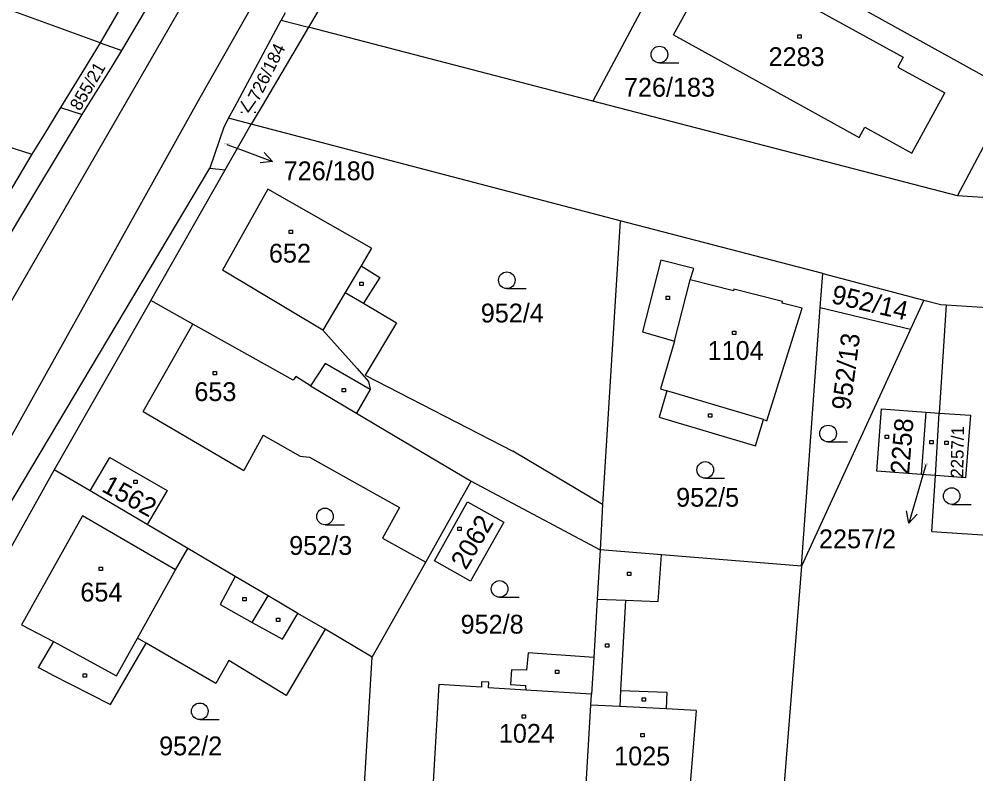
# Model space of a CAD drawing. Extents: x -711879 to -711361, y -1048782 to -1048177.
# Drawn here: x -711571.3 to -711485, y -1048372.4 to -1048304.3 of the extents above; entities that cross this region are included whole.
import ezdxf

# ---------------------------------------------------------------- set-up
doc = ezdxf.new("R2010")
doc.units = 0
for name, color, linetype in [('Vrstva 1', 7, 'Continuous'), ('Vrstva 13', 7, 'Continuous'), ('Vrstva 14', 7, 'Continuous'), ('Vrstva 15', 7, 'Continuous'), ('Vrstva 16', 7, 'Continuous'), ('Vrstva 2', 7, 'Continuous'), ('Vrstva 23', 7, 'Continuous'), ('Vrstva 25', 7, 'Continuous'), ('Vrstva 46', 7, 'Continuous')]:
    doc.layers.add(name, color=color, linetype=linetype)

msp = doc.modelspace()

# ---------------------------------------------------------------- linework, layer by layer
at = {"layer": 'Vrstva 1'}
for p, q in [((-711524.36, -1048257.61), (-711555.05, -1048311.45)), ((-711548.53, -1048279.74), (-711564.04, -1048306.47)), ((-711562.07, -1048307.17), (-711547.11, -1048281.75)), ((-711532.03, -1048282.6), (-711545.23, -1048305.07)), ((-711545.71, -1048284.16), (-711558.97, -1048307.13)), ((-711510.59, -1048294.89), (-711519.58, -1048311.73)), ((-711481.7, -1048310.92), (-711510.59, -1048294.89)), ((-711564.04, -1048306.47), (-711576.93, -1048301.82)), ((-711547.33, -1048303.79), (-711547.7, -1048304.44)), ((-711551.88, -1048312.25), (-711547.7, -1048304.44)), ((-711547.7, -1048304.44), (-711545.23, -1048305.07)), ((-711545.23, -1048305.07), (-711546.26, -1048306.81)), ((-711519.58, -1048311.73), (-711545.23, -1048305.07)), ((-711558.97, -1048307.13), (-711582.21, -1048347.23)), ((-711564.04, -1048306.47), (-711565.04, -1048308.11)), ((-711564.04, -1048306.47), (-711562.07, -1048307.17)), ((-711562.95, -1048308.63), (-711562.07, -1048307.17)), ((-711546.26, -1048306.81), (-711549.42, -1048312.18)), ((-711565.04, -1048308.11), (-711565.22, -1048308.4)), ((-711565.22, -1048308.4), (-711567.62, -1048312.33)), ((-711565.65, -1048312.95), (-711562.95, -1048308.63)), ((-711587.33, -1048311.04), (-711570.19, -1048316.54)), ((-711555.05, -1048311.45), (-711583.43, -1048362.34)), ((-711486.65, -1048320.28), (-711481.7, -1048310.92)), ((-711567.62, -1048312.33), (-711569.16, -1048314.85)), ((-711567.62, -1048312.33), (-711565.65, -1048312.95)), ((-711552.44, -1048313.29), (-711551.88, -1048312.25)), ((-711549.42, -1048312.18), (-711550.4, -1048313.82)), ((-711486.65, -1048320.28), (-711519.58, -1048311.73)), ((-711569.92, -1048320.04), (-711565.65, -1048312.95)), ((-711552.44, -1048313.29), (-711552.87, -1048314.09)), ((-711550.4, -1048313.82), (-711552.44, -1048313.29)), ((-711552.87, -1048314.09), (-711554.12, -1048317.79)), ((-711552.75, -1048317.94), (-711550.4, -1048313.82)), ((-711517.11, -1048322.54), (-711550.4, -1048313.82)), ((-711569.16, -1048314.85), (-711570.19, -1048316.54)), ((-711570.19, -1048316.54), (-711580.92, -1048334.45)), ((-711584.04, -1048367.95), (-711554.12, -1048317.79)), ((-711559.47, -1048329.72), (-711552.75, -1048317.94)), ((-711554.12, -1048317.79), (-711552.75, -1048317.94)), ((-711588.19, -1048350.31), (-711569.92, -1048320.04)), ((-711548.89, -1048319.68), (-711552.99, -1048326.98)), ((-711539.55, -1048325), (-711548.89, -1048319.68)), ((-711462.88, -1048321.96), (-711486.65, -1048320.28)), ((-711517.11, -1048322.54), (-711518.68, -1048348.13)), ((-711498.82, -1048327.29), (-711517.11, -1048322.54)), ((-711539.55, -1048325), (-711540.49, -1048326.6)), ((-711513.42, -1048326.1), (-711515.08, -1048332.56)), ((-711510.46, -1048326.85), (-711513.42, -1048326.1)), ((-711543.93, -1048332.41), (-711552.99, -1048326.98)), ((-711540.49, -1048326.6), (-711538.8, -1048327.64)), ((-711510.77, -1048327.87), (-711510.46, -1048326.85)), ((-711538.8, -1048327.64), (-711540.26, -1048329.98)), ((-711506.86, -1048328.85), (-711510.77, -1048327.87)), ((-711499.06, -1048330.36), (-711498.82, -1048327.29)), ((-711498.82, -1048327.29), (-711489.7, -1048329.69)), ((-711506.83, -1048328.7), (-711506.86, -1048328.85)), ((-711502.45, -1048329.81), (-711506.83, -1048328.7)), ((-711559.47, -1048329.72), (-711568.18, -1048345.01)), ((-711555.66, -1048331.85), (-711559.47, -1048329.72)), ((-711489.7, -1048329.69), (-711490.91, -1048332.3)), ((-711489.7, -1048329.69), (-711488.17, -1048330.09)), ((-711540.26, -1048329.98), (-711537.29, -1048331.74)), ((-711503.86, -1048340.57), (-711500.68, -1048330.41)), ((-711502.48, -1048329.96), (-711502.45, -1048329.81)), ((-711500.68, -1048330.41), (-711502.48, -1048329.96)), ((-711500.73, -1048353.71), (-711499.06, -1048330.36)), ((-711499.06, -1048330.36), (-711490.91, -1048332.3)), ((-711487.69, -1048330.12), (-711488.3, -1048339.88)), ((-711488.17, -1048330.09), (-711487.69, -1048330.12)), ((-711487.69, -1048330.12), (-711468.27, -1048331.34)), ((-711560.16, -1048339.74), (-711555.66, -1048331.85)), ((-711546.6, -1048336.92), (-711555.66, -1048331.85)), ((-711537.29, -1048331.74), (-711540.13, -1048336.47)), ((-711490.91, -1048332.3), (-711500.73, -1048353.71)), ((-711543.93, -1048332.41), (-711540.85, -1048335.86)), ((-711515.08, -1048332.56), (-711512.2, -1048333.41)), ((-711512.2, -1048333.41), (-711513.47, -1048337.71)), ((-711543.74, -1048335.41), (-711545.05, -1048337.44)), ((-711539.66, -1048337.75), (-711543.74, -1048335.41)), ((-711546.37, -1048336.57), (-711546.6, -1048336.92)), ((-711545.05, -1048337.44), (-711546.37, -1048336.57)), ((-711540.85, -1048335.86), (-711539.8, -1048337.04)), ((-711540.13, -1048336.47), (-711526.79, -1048343.33)), ((-711545.05, -1048337.44), (-711540.9, -1048339.9)), ((-711539.8, -1048337.04), (-711539.66, -1048337.75)), ((-711512.89, -1048337.89), (-711513.59, -1048340.26)), ((-711513.47, -1048337.71), (-711512.89, -1048337.89)), ((-711560.16, -1048339.74), (-711551.07, -1048345.07)), ((-711540.9, -1048339.9), (-711538.87, -1048341.1)), ((-711493.94, -1048345.11), (-711493.51, -1048339.51)), ((-711493.51, -1048339.51), (-711489.5, -1048339.79)), ((-711489.5, -1048339.79), (-711489.93, -1048345.42)), ((-711489.5, -1048339.79), (-711488.3, -1048339.88)), ((-711488.65, -1048345.52), (-711488.3, -1048339.88)), ((-711488.3, -1048339.88), (-711485.48, -1048340.08)), ((-711485.48, -1048340.08), (-711485.92, -1048345.73)), ((-711513.59, -1048340.26), (-711504.88, -1048342.84)), ((-711504.88, -1048342.84), (-711504.17, -1048340.47)), ((-711504.17, -1048340.47), (-711503.86, -1048340.57)), ((-711538.87, -1048341.1), (-711530.54, -1048346.03)), ((-711549.31, -1048341.87), (-711551.07, -1048345.07)), ((-711518.68, -1048348.13), (-711526.79, -1048343.33)), ((-711564.95, -1048346.91), (-711563.16, -1048343.88)), ((-711563.16, -1048343.88), (-711557.99, -1048346.87)), ((-711568.18, -1048345.01), (-711582.56, -1048370.66)), ((-711564.95, -1048346.91), (-711568.18, -1048345.01)), ((-711489.93, -1048345.42), (-711493.94, -1048345.11)), ((-711533.2, -1048350.75), (-711530.54, -1048346.03)), ((-711530.54, -1048346.03), (-711518.92, -1048352.21)), ((-711488.65, -1048345.52), (-711489.93, -1048345.42)), ((-711488.97, -1048350.58), (-711488.65, -1048345.52)), ((-711485.92, -1048345.73), (-711488.65, -1048345.52)), ((-711559.8, -1048349.94), (-711564.95, -1048346.91)), ((-711557.99, -1048346.87), (-711559.8, -1048349.94)), ((-711533.87, -1048353.2), (-711530.87, -1048347.88)), ((-711530.87, -1048347.88), (-711527.6, -1048349.72)), ((-711518.68, -1048348.13), (-711518.92, -1048352.21)), ((-711565.64, -1048349.16), (-711571.12, -1048358.99)), ((-711557.23, -1048354.03), (-711565.64, -1048349.16)), ((-711556.11, -1048352.11), (-711559.8, -1048349.94)), ((-711527.6, -1048349.72), (-711530.6, -1048355.05)), ((-711534.65, -1048353.32), (-711533.2, -1048350.75)), ((-711488.97, -1048350.58), (-711470.22, -1048351.75)), ((-711557.23, -1048354.03), (-711556.11, -1048352.11)), ((-711551.85, -1048354.62), (-711556.11, -1048352.11)), ((-711518.92, -1048352.21), (-711519.18, -1048356.66)), ((-711513.38, -1048352.67), (-711518.92, -1048352.21)), ((-711500.73, -1048353.71), (-711513.38, -1048352.67)), ((-711539.49, -1048361.89), (-711534.65, -1048353.32)), ((-711530.6, -1048355.05), (-711533.87, -1048353.2)), ((-711500.73, -1048353.71), (-711502.65, -1048377.83)), ((-711548.88, -1048356.37), (-711551.85, -1048354.62)), ((-711546.18, -1048357.96), (-711548.88, -1048356.37)), ((-711519.18, -1048356.66), (-711519.49, -1048361.93)), ((-711543.74, -1048359.39), (-711546.18, -1048357.96)), ((-711571.12, -1048358.99), (-711568.25, -1048360.49)), ((-711543.74, -1048359.39), (-711547.26, -1048365.37)), ((-711539.49, -1048361.89), (-711543.74, -1048359.39)), ((-711568.25, -1048360.49), (-711569.62, -1048362.84)), ((-711563.09, -1048366.18), (-711559.89, -1048360.64)), ((-711553.59, -1048364.27), (-711559.89, -1048360.64)), ((-711525.39, -1048361.52), (-711525.55, -1048363.07)), ((-711519.49, -1048361.93), (-711525.39, -1048361.52)), ((-711552.41, -1048362.22), (-711553.59, -1048364.27)), ((-711547.26, -1048365.37), (-711552.41, -1048362.22)), ((-711540.33, -1048375.71), (-711539.49, -1048361.89)), ((-711519.49, -1048361.93), (-711519.69, -1048365.25)), ((-711568.43, -1048363.47), (-711569.62, -1048362.84)), ((-711526.9, -1048363.05), (-711527.01, -1048364.37)), ((-711525.55, -1048363.07), (-711526.9, -1048363.05)), ((-711568.43, -1048363.47), (-711563.09, -1048366.18)), ((-711529.61, -1048364.13), (-711529.63, -1048364.61)), ((-711528.96, -1048364.16), (-711529.61, -1048364.13)), ((-711528.98, -1048364.66), (-711528.96, -1048364.16)), ((-711533.47, -1048364.37), (-711533.97, -1048373.17)), ((-711529.63, -1048364.61), (-711533.47, -1048364.37)), ((-711525.61, -1048364.87), (-711528.98, -1048364.66)), ((-711527.01, -1048364.37), (-711525.64, -1048364.47)), ((-711525.64, -1048364.47), (-711525.61, -1048364.87)), ((-711519.75, -1048366.23), (-711519.69, -1048365.25)), ((-711520.23, -1048374.45), (-711519.75, -1048366.23))]:
    msp.add_line(p, q, dxfattribs=at)
for points in [[(-711512.3, -1048305.77), (-711508.33, -1048298.55), (-711491.56, -1048307.79), (-711492.04, -1048308.69), (-711487.8, -1048310.99)], [(-711512.3, -1048305.77), (-711495.53, -1048315.02), (-711495.01, -1048314.08), (-711490.78, -1048316.44), (-711487.8, -1048310.99)], [(-711549.31, -1048341.87), (-711545.99, -1048343.76), (-711545.15, -1048343.86), (-711537.03, -1048348.4), (-711538.54, -1048351.16), (-711534.65, -1048353.32)]]:
    msp.add_lwpolyline(points, dxfattribs=at)
at = {"layer": 'Vrstva 13'}
for p, q in [((-711552.59, -1048315.65), (-711551.28, -1048316.14)), ((-711489.51, -1048344.55), (-711490.21, -1048346.93))]:
    msp.add_line(p, q, dxfattribs=at)
at = {"layer": 'Vrstva 16'}
for p, q in [((-711551.28, -1048316.14), (-711548.467, -1048317.184)), ((-711548.467, -1048317.184), (-711549.231, -1048316.367)), ((-711548.467, -1048317.184), (-711549.579, -1048317.304)), ((-711490.21, -1048346.93), (-711491.052, -1048349.809)), ((-711491.052, -1048349.809), (-711491.251, -1048348.708)), ((-711491.052, -1048349.809), (-711490.292, -1048348.989))]:
    msp.add_line(p, q, dxfattribs=at)
at = {"layer": 'Vrstva 2'}
for p, q in [((-711540.49, -1048326.6), (-711541.91, -1048329)), ((-711512.2, -1048333.41), (-711510.77, -1048327.87)), ((-711541.91, -1048329), (-711543.93, -1048332.41)), ((-711541.91, -1048329), (-711540.26, -1048329.98)), ((-711539.66, -1048337.75), (-711540.9, -1048339.9)), ((-711504.17, -1048340.47), (-711512.89, -1048337.89)), ((-711513.67, -1048356.88), (-711513.38, -1048352.67)), ((-711560.66, -1048360.19), (-711557.23, -1048354.03)), ((-711551.85, -1048354.62), (-711553.19, -1048357.16)), ((-711550.31, -1048358.77), (-711548.88, -1048356.37)), ((-711553.19, -1048357.16), (-711550.31, -1048358.77)), ((-711519.18, -1048356.66), (-711516.61, -1048356.77)), ((-711516.61, -1048356.77), (-711517.06, -1048364.9)), ((-711516.61, -1048356.77), (-711513.67, -1048356.88)), ((-711547.58, -1048360.29), (-711546.18, -1048357.96)), ((-711550.31, -1048358.77), (-711547.58, -1048360.29)), ((-711568.25, -1048360.49), (-711562.56, -1048363.6)), ((-711562.56, -1048363.6), (-711560.66, -1048360.19)), ((-711559.89, -1048360.64), (-711560.66, -1048360.19)), ((-711519.69, -1048365.25), (-711525.61, -1048364.87)), ((-711517.06, -1048364.9), (-711517.12, -1048366.36)), ((-711517.06, -1048364.9), (-711512.9, -1048365.06)), ((-711512.9, -1048365.06), (-711512.94, -1048366.58)), ((-711517.12, -1048366.36), (-711519.75, -1048366.23)), ((-711512.94, -1048366.58), (-711517.12, -1048366.36)), ((-711510.23, -1048366.72), (-711512.94, -1048366.58)), ((-711510.23, -1048366.72), (-711510.91, -1048374.85))]:
    msp.add_line(p, q, dxfattribs=at)
at = {"layer": 'Vrstva 23'}
for p, q in [((-711513.56, -1048308.29), (-711511.81, -1048308.29)), ((-711551.33, -1048311.745), (-711550.66, -1048312.75)), ((-711550.66, -1048312.75), (-711549.99, -1048311.745)), ((-711551.33, -1048312.75), (-711551.196, -1048312.75)), ((-711550.124, -1048312.75), (-711549.99, -1048312.75)), ((-711527.33, -1048328.65), (-711525.58, -1048328.65)), ((-711498.33, -1048342.48), (-711496.58, -1048342.48)), ((-711509.42, -1048345.76), (-711507.67, -1048345.76)), ((-711487.18, -1048348.12), (-711485.43, -1048348.12)), ((-711543.74, -1048349.96), (-711541.99, -1048349.96)), ((-711527.98, -1048356.5), (-711526.23, -1048356.5)), ((-711555.04, -1048367.54), (-711553.29, -1048367.54))]:
    msp.add_line(p, q, dxfattribs=at)
for centre in [(-711513.56, -1048307.54), (-711527.33, -1048327.9), (-711498.33, -1048341.73), (-711509.42, -1048345.01), (-711487.18, -1048347.37), (-711543.74, -1048349.21), (-711527.98, -1048355.75), (-711555.04, -1048366.79)]:
    msp.add_circle(centre, 0.75, dxfattribs=at)
at = {"layer": 'Vrstva 25'}
for p, q in [((-711501.07, -1048305.76), (-711500.77, -1048305.76)), ((-711501.07, -1048306.06), (-711501.07, -1048305.76)), ((-711500.77, -1048306.06), (-711501.07, -1048306.06)), ((-711500.77, -1048305.76), (-711500.77, -1048306.06)), ((-711546.98, -1048323.39), (-711546.68, -1048323.39)), ((-711546.98, -1048323.69), (-711546.98, -1048323.39)), ((-711546.68, -1048323.69), (-711546.98, -1048323.69)), ((-711546.68, -1048323.39), (-711546.68, -1048323.69)), ((-711540.59, -1048328.06), (-711540.29, -1048328.06)), ((-711540.59, -1048328.36), (-711540.59, -1048328.06)), ((-711540.29, -1048328.36), (-711540.59, -1048328.36)), ((-711540.29, -1048328.06), (-711540.29, -1048328.36)), ((-711512.96, -1048329.34), (-711512.66, -1048329.34)), ((-711512.96, -1048329.64), (-711512.96, -1048329.34)), ((-711512.66, -1048329.64), (-711512.96, -1048329.64)), ((-711512.66, -1048329.34), (-711512.66, -1048329.64)), ((-711506.96, -1048332.5), (-711506.66, -1048332.5)), ((-711506.96, -1048332.8), (-711506.96, -1048332.5)), ((-711506.66, -1048332.8), (-711506.96, -1048332.8)), ((-711506.66, -1048332.5), (-711506.66, -1048332.8)), ((-711553.82, -1048336.12), (-711553.52, -1048336.12)), ((-711553.82, -1048336.42), (-711553.82, -1048336.12)), ((-711553.52, -1048336.42), (-711553.82, -1048336.42)), ((-711553.52, -1048336.12), (-711553.52, -1048336.42)), ((-711542.2, -1048337.67), (-711541.9, -1048337.67)), ((-711542.2, -1048337.97), (-711542.2, -1048337.67)), ((-711541.9, -1048337.97), (-711542.2, -1048337.97)), ((-711541.9, -1048337.67), (-711541.9, -1048337.97)), ((-711509.14, -1048339.94), (-711508.84, -1048339.94)), ((-711509.14, -1048340.24), (-711509.14, -1048339.94)), ((-711508.84, -1048339.94), (-711508.84, -1048340.24)), ((-711508.84, -1048340.24), (-711509.14, -1048340.24)), ((-711493.18, -1048341.89), (-711492.88, -1048341.89)), ((-711493.18, -1048342.19), (-711493.18, -1048341.89)), ((-711492.88, -1048342.19), (-711493.18, -1048342.19)), ((-711492.88, -1048341.89), (-711492.88, -1048342.19)), ((-711489.15, -1048342.37), (-711488.85, -1048342.37)), ((-711489.15, -1048342.67), (-711489.15, -1048342.37)), ((-711488.85, -1048342.67), (-711489.15, -1048342.67)), ((-711488.85, -1048342.37), (-711488.85, -1048342.67)), ((-711487.79, -1048342.42), (-711487.49, -1048342.42)), ((-711487.79, -1048342.72), (-711487.79, -1048342.42)), ((-711487.49, -1048342.72), (-711487.79, -1048342.72)), ((-711487.49, -1048342.42), (-711487.49, -1048342.72)), ((-711560.99, -1048345.93), (-711560.69, -1048345.93)), ((-711560.99, -1048346.23), (-711560.99, -1048345.93)), ((-711560.69, -1048345.93), (-711560.69, -1048346.23)), ((-711560.69, -1048346.23), (-711560.99, -1048346.23)), ((-711531.74, -1048350.18), (-711531.44, -1048350.18)), ((-711531.74, -1048350.48), (-711531.74, -1048350.18)), ((-711531.44, -1048350.48), (-711531.74, -1048350.48)), ((-711531.44, -1048350.18), (-711531.44, -1048350.48)), ((-711564.13, -1048353.79), (-711563.83, -1048353.79)), ((-711564.13, -1048354.09), (-711564.13, -1048353.79)), ((-711563.83, -1048353.79), (-711563.83, -1048354.09)), ((-711563.83, -1048354.09), (-711564.13, -1048354.09)), ((-711516.45, -1048354.23), (-711516.15, -1048354.23)), ((-711516.45, -1048354.53), (-711516.45, -1048354.23)), ((-711516.15, -1048354.53), (-711516.45, -1048354.53)), ((-711516.15, -1048354.23), (-711516.15, -1048354.53)), ((-711551.16, -1048356.52), (-711550.86, -1048356.52)), ((-711551.16, -1048356.82), (-711551.16, -1048356.52)), ((-711550.86, -1048356.52), (-711550.86, -1048356.82)), ((-711550.86, -1048356.82), (-711551.16, -1048356.82)), ((-711548.12, -1048358.4), (-711547.82, -1048358.4)), ((-711548.12, -1048358.7), (-711548.12, -1048358.4)), ((-711547.82, -1048358.7), (-711548.12, -1048358.7)), ((-711547.82, -1048358.4), (-711547.82, -1048358.7)), ((-711518.43, -1048360.7), (-711518.13, -1048360.7)), ((-711518.43, -1048361), (-711518.43, -1048360.7)), ((-711518.13, -1048360.7), (-711518.13, -1048361)), ((-711518.13, -1048361), (-711518.43, -1048361)), ((-711565.56, -1048363.41), (-711565.26, -1048363.41)), ((-711565.56, -1048363.71), (-711565.56, -1048363.41)), ((-711565.26, -1048363.41), (-711565.26, -1048363.71)), ((-711522.93, -1048363.09), (-711522.63, -1048363.09)), ((-711522.93, -1048363.39), (-711522.93, -1048363.09)), ((-711522.63, -1048363.39), (-711522.93, -1048363.39)), ((-711522.63, -1048363.09), (-711522.63, -1048363.39)), ((-711565.26, -1048363.71), (-711565.56, -1048363.71)), ((-711515.11, -1048365.57), (-711514.81, -1048365.57)), ((-711515.11, -1048365.87), (-711515.11, -1048365.57)), ((-711514.81, -1048365.87), (-711515.11, -1048365.87)), ((-711514.81, -1048365.57), (-711514.81, -1048365.87)), ((-711525.94, -1048367.1), (-711525.64, -1048367.1)), ((-711525.94, -1048367.4), (-711525.94, -1048367.1)), ((-711525.64, -1048367.4), (-711525.94, -1048367.4)), ((-711525.64, -1048367.1), (-711525.64, -1048367.4)), ((-711515.22, -1048368.79), (-711514.92, -1048368.79)), ((-711515.22, -1048369.09), (-711515.22, -1048368.79)), ((-711514.92, -1048369.09), (-711515.22, -1048369.09)), ((-711514.92, -1048368.79), (-711514.92, -1048369.09))]:
    msp.add_line(p, q, dxfattribs=at)
at = {"layer": 'Vrstva 46'}
for p, q in [((-711545.23, -1048305.07), (-711545.23, -1048305.07)), ((-711564.04, -1048306.47), (-711564.04, -1048306.47)), ((-711546.26, -1048306.81), (-711546.26, -1048306.81)), ((-711565.22, -1048308.4), (-711565.22, -1048308.4)), ((-711549.42, -1048312.18), (-711549.42, -1048312.18)), ((-711569.16, -1048314.85), (-711569.16, -1048314.85)), ((-711548.89, -1048319.68), (-711548.89, -1048319.68)), ((-711486.65, -1048320.28), (-711486.65, -1048320.28)), ((-711517.11, -1048322.54), (-711517.11, -1048322.54)), ((-711539.55, -1048325), (-711539.55, -1048325)), ((-711510.77, -1048327.87), (-711510.77, -1048327.87)), ((-711498.82, -1048327.29), (-711498.82, -1048327.29)), ((-711506.86, -1048328.85), (-711506.86, -1048328.85)), ((-711506.83, -1048328.7), (-711506.83, -1048328.7)), ((-711559.47, -1048329.72), (-711559.47, -1048329.72)), ((-711489.7, -1048329.69), (-711489.7, -1048329.69)), ((-711502.48, -1048329.96), (-711502.48, -1048329.96)), ((-711502.45, -1048329.81), (-711502.45, -1048329.81)), ((-711500.68, -1048330.41), (-711500.68, -1048330.41)), ((-711499.06, -1048330.36), (-711499.06, -1048330.36)), ((-711488.17, -1048330.09), (-711488.17, -1048330.09)), ((-711487.69, -1048330.12), (-711487.69, -1048330.12)), ((-711490.91, -1048332.3), (-711490.91, -1048332.3)), ((-711512.2, -1048333.41), (-711512.2, -1048333.41)), ((-711513.47, -1048337.71), (-711513.47, -1048337.71)), ((-711512.89, -1048337.89), (-711512.89, -1048337.89)), ((-711560.16, -1048339.74), (-711560.16, -1048339.74)), ((-711504.17, -1048340.47), (-711504.17, -1048340.47)), ((-711503.86, -1048340.57), (-711503.86, -1048340.57)), ((-711548.94, -1048342.08), (-711548.94, -1048342.08)), ((-711526.79, -1048343.33), (-711526.79, -1048343.33)), ((-711563.16, -1048343.88), (-711563.16, -1048343.88)), ((-711568.18, -1048345.01), (-711568.18, -1048345.01)), ((-711550.81, -1048345.36), (-711550.81, -1048345.36)), ((-711564.95, -1048346.91), (-711564.95, -1048346.91)), ((-711557.99, -1048346.87), (-711557.99, -1048346.87)), ((-711518.68, -1048348.13), (-711518.68, -1048348.13)), ((-711565.64, -1048349.16), (-711565.64, -1048349.16)), ((-711559.8, -1048349.94), (-711559.8, -1048349.94)), ((-711518.92, -1048352.21), (-711518.92, -1048352.21)), ((-711534.65, -1048353.32), (-711534.65, -1048353.32)), ((-711500.73, -1048353.71), (-711500.73, -1048353.71)), ((-711557.23, -1048354.03), (-711557.23, -1048354.03)), ((-711571.12, -1048358.99), (-711571.12, -1048358.99)), ((-711539.49, -1048361.89), (-711539.49, -1048361.89)), ((-711519.49, -1048361.93), (-711519.49, -1048361.93)), ((-711568.43, -1048363.47), (-711568.43, -1048363.47)), ((-711528.98, -1048364.66), (-711528.98, -1048364.66)), ((-711525.61, -1048364.87), (-711525.61, -1048364.87)), ((-711519.69, -1048365.25), (-711519.69, -1048365.25)), ((-711510.23, -1048366.72), (-711510.23, -1048366.72))]:
    msp.add_line(p, q, dxfattribs=at)

# ---------------------------------------------------------------- texts
at = {"layer": 'Vrstva 14'}
for s, height, rotation, p in [('726/184', 1.14, 63.43497, (-711549.742, -1048311.854)), ('855/21', 1.14, 59.63832, (-711565.857, -1048312.695)), ('952/14', 1.7, 346.79889, (-711498.13, -1048329.94)), ('952/13', 1.7, 82.52847, (-711496.34, -1048339.69))]:
    msp.add_text(s, height=height, rotation=rotation, dxfattribs=at).set_placement(p)
for s, height, p in [('726/183', 1.7, (-711516.759, -1048311.34)), ('726/180', 0.1, (-711552.871, -1048315.65)), ('952/4', 1.7, (-711529.68, -1048331.71)), ('952/5', 1.7, (-711512.05, -1048348.33)), ('952/3', 1.7, (-711546.97, -1048352.68)), ('952/8', 1.7, (-711531.5, -1048359.78)), ('952/2', 1.7, (-711558.71, -1048370.76))]:
    msp.add_text(s, height=height, dxfattribs=at).set_placement(p)
at = {"layer": 'Vrstva 15'}
for s, height, p in [('2283', 1.7, (-711503.706, -1048308.58)), ('652', 1.7, (-711548.8, -1048326.31)), ('1104', 1.7, (-711509.21, -1048335.09)), ('653', 1.7, (-711555.53, -1048338.8)), ('2257/2', 0.1, (-711489.761, -1048344.55)), ('654', 1.7, (-711565.82, -1048356.89)), ('1024', 1.7, (-711528.05, -1048369.63)), ('1025', 1.7, (-711517.64, -1048371.67))]:
    msp.add_text(s, height=height, dxfattribs=at).set_placement(p)
for s, height, rotation, p in [('2258', 1.7, 85.30506, (-711491.031, -1048345.462)), ('2257/1', 1.14, 89.09064, (-711486.133, -1048345.729)), ('1562', 1.7, 331.14438, (-711564, -1048346.89)), ('2062', 1.7, 59.50017, (-711531.02, -1048354.11))]:
    msp.add_text(s, height=height, rotation=rotation, dxfattribs=at).set_placement(p)
at = {"layer": 'Vrstva 16'}
for s, p in [('726/180', (-711547.47, -1048318.88)), ('2257/2', (-711499.155, -1048352.08))]:
    msp.add_text(s, height=1.7, dxfattribs=at).set_placement(p)

doc.saveas('drawing.dxf')
